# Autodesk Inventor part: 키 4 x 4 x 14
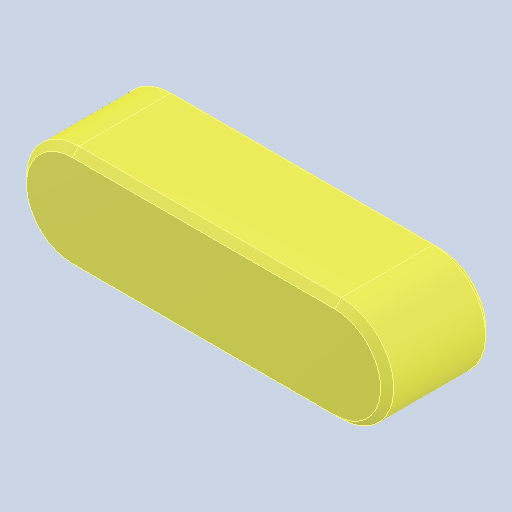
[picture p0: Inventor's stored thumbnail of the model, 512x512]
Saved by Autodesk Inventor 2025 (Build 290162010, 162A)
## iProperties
Created: 2024-07
Part Number: 키 4 x 4 x 14
Material: 강철, 연강
Description: 키 및 해당 키홈
Document SubType Name: Modeling
Designer: Admin
Density: 7.85 g/cm^3
Appearance: 기본값
Author: jhkim
Sending System: Autodesk Inventor 2025
Preprocessor: ST-DEVELOPER v20
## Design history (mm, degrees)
feature "Solid1"
node "솔리드1"
